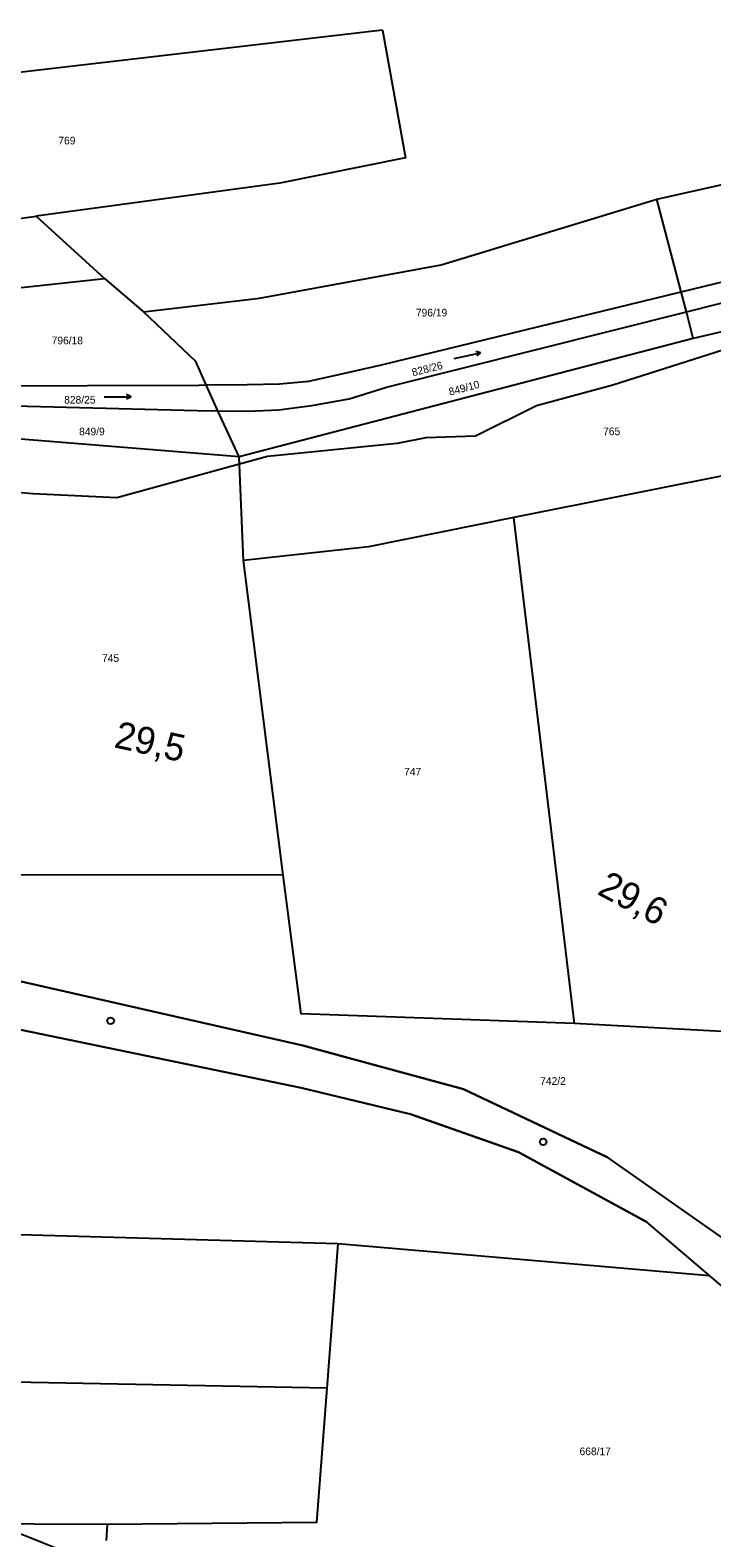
# Model space of a CAD drawing. Extents: x -794765 to -785424, y -1118958 to -1108731.
# Drawn here: x -788796.9 to -788645.5, y -1114795.4 to -1114460.5 of the extents above; entities that cross this region are included whole.
import ezdxf

# ---------------------------------------------------------------- set-up
doc = ezdxf.new("R2010")
doc.units = 0
for name, color, linetype in [('Level 66', 7, 'Continuous'), ('Level 73', 7, 'Continuous'), ('Level 75', 7, 'Continuous'), ('Level 76', 7, 'Continuous'), ('Level 81', 7, 'Continuous'), ('Vrstva 1', 7, 'Continuous'), ('Vrstva 53', 7, 'Continuous')]:
    doc.layers.add(name, color=color, linetype=linetype)

msp = doc.modelspace()

# ---------------------------------------------------------------- linework, layer by layer
at = {"layer": 'Level 66'}
for p, q in [((-788702.69, -1114533.48), (-788696.82, -1114532.23)), ((-788696.82, -1114532.23), (-788697.88, -1114531.94)), ((-788696.82, -1114532.23), (-788697.67, -1114532.93)), ((-788780.48, -1114541.97), (-788774.48, -1114541.97)), ((-788774.48, -1114541.97), (-788775.46, -1114541.47)), ((-788774.48, -1114541.97), (-788775.46, -1114542.47))]:
    msp.add_line(p, q, dxfattribs=at)
at = {"layer": 'Level 75'}
for p, q in [((-788657.65, -1114498.07), (-788604.55, -1114486.18)), ((-788652.28, -1114518.65), (-788657.65, -1114498.07)), ((-788795.54, -1114501.83), (-788780.41, -1114515.68)), ((-788780.41, -1114515.68), (-788771.75, -1114523.06)), ((-788651.12, -1114523.09), (-788652.28, -1114518.65)), ((-788602.26, -1114517.95), (-788649.58, -1114529.02)), ((-788649.58, -1114529.02), (-788651.12, -1114523.09)), ((-788649.58, -1114529.02), (-788750.44, -1114555.28)), ((-788755.23, -1114545.05), (-788757.8, -1114539.34)), ((-788750.44, -1114555.28), (-788755.23, -1114545.05)), ((-788750.44, -1114555.28), (-788812.08, -1114550.36)), ((-788593.73, -1114549.62), (-788689.42, -1114568.81)), ((-788749.5, -1114578.32), (-788750.44, -1114555.28)), ((-788676.01, -1114681.19), (-788689.42, -1114568.81)), ((-788740.67, -1114648.25), (-788749.5, -1114578.32)), ((-788740.67, -1114648.25), (-788809.85, -1114648.14)), ((-788578.67, -1114686.45), (-788676.01, -1114681.19)), ((-788728.52, -1114730.08), (-788889.17, -1114725.56)), ((-788728.52, -1114730.08), (-788730.98, -1114762.14)), ((-788646.02, -1114737.19), (-788728.52, -1114730.08)), ((-788730.98, -1114762.14), (-788891.11, -1114759.07)), ((-788779.95, -1114796.03), (-788779.75, -1114792.43))]:
    msp.add_line(p, q, dxfattribs=at)
for points in [[(-788718.63, -1114460.53), (-788817.27, -1114472.02), (-788860.22, -1114476)], [(-788718.63, -1114460.53), (-788713.48, -1114488.88), (-788741.43, -1114494.53), (-788795.54, -1114501.83)], [(-788652.28, -1114518.65), (-788624.54, -1114511.9), (-788617.46, -1114509.39), (-788611.73, -1114507.29), (-788607.29, -1114504.53), (-788603.63, -1114501.82), (-788598.93, -1114496.8), (-788594.19, -1114490.76), (-788587.23, -1114480)], [(-788651.12, -1114523.09), (-788623.58, -1114516.16), (-788616, -1114514.07), (-788610.11, -1114511.52), (-788604.65, -1114507.97), (-788600.76, -1114505.15), (-788595.29, -1114500.07), (-788590.4, -1114494.22), (-788581.92, -1114481.24), (-788580.1, -1114477.46)], [(-788860.65, -1114495.76), (-788860.57, -1114507.36), (-788820.58, -1114505.34), (-788795.54, -1114501.83)], [(-788771.75, -1114523.06), (-788745.95, -1114520.06), (-788705.61, -1114512.65), (-788657.65, -1114498.07)], [(-788812.75, -1114539.42), (-788813.99, -1114519.29), (-788780.41, -1114515.68)], [(-788757.8, -1114539.34), (-788748.69, -1114539.26), (-788741.49, -1114539.08), (-788735.01, -1114538.51), (-788727.34, -1114536.81), (-788718.84, -1114534.86), (-788652.28, -1114518.65)], [(-788757.8, -1114539.34), (-788760.13, -1114534.14), (-788771.75, -1114523.06)], [(-788755.23, -1114545.05), (-788748.54, -1114545.13), (-788741.64, -1114544.89), (-788734.31, -1114543.93), (-788726.02, -1114542.39), (-788717.73, -1114539.86), (-788651.12, -1114523.09)], [(-788812.75, -1114539.42), (-788809.05, -1114539.56), (-788759.42, -1114539.35), (-788757.8, -1114539.34)], [(-788812.49, -1114543.63), (-788809.16, -1114543.75), (-788759.81, -1114544.99), (-788755.23, -1114545.05)], [(-788689.42, -1114568.81), (-788721.73, -1114575.26), (-788749.5, -1114578.32)], [(-788676.01, -1114681.19), (-788736.73, -1114679), (-788740.67, -1114648.25)], [(-788630.19, -1114737.89), (-788640.82, -1114730.42), (-788668.56, -1114710.95), (-788700.64, -1114695.78), (-788736.3, -1114686.03), (-788817.52, -1114667.59)], [(-788818.39, -1114678.6), (-788736.68, -1114695.45), (-788712.4, -1114701.34), (-788688.38, -1114709.77), (-788660.09, -1114725.18), (-788646.02, -1114737.19)], [(-788646.02, -1114737.19), (-788635.61, -1114746.08), (-788616.47, -1114768.17)], [(-788730.98, -1114762.14), (-788733.28, -1114792.03), (-788779.75, -1114792.43)], [(-788779.75, -1114792.43), (-788828.56, -1114792.24), (-788890.53, -1114788.77)]]:
    msp.add_lwpolyline(points, dxfattribs=at)
at = {"layer": 'Level 81'}
for points in [[(-788641.17, -1114531.05), (-788667.46, -1114539.39), (-788684.41, -1114543.99), (-788697.98, -1114550.72), (-788708.99, -1114551.11), (-788715.35, -1114552.35), (-788744.16, -1114555.22), (-788750.37, -1114556.93), (-788777.65, -1114564.42), (-788796.29, -1114563.51), (-788811.71, -1114562.17)], [(-789061.76, -1114798.86), (-789055.53, -1114793.64), (-789048.32, -1114789.44), (-789035.18, -1114782.71), (-789024.16, -1114779.36), (-789001.7, -1114774.78), (-788981.9, -1114772.16), (-788976.7, -1114771.48), (-788957.63, -1114771.54), (-788907.65, -1114776.78), (-788896.06, -1114778.62), (-788892.28, -1114779.23), (-788858.94, -1114784.55), (-788838.18, -1114786.31), (-788830.99, -1114788.02), (-788814.89, -1114790.61), (-788807.51, -1114792.32), (-788800.07, -1114794.04), (-788785.25, -1114800.01)]]:
    msp.add_lwpolyline(points, dxfattribs=at)
at = {"layer": 'Vrstva 1'}
for centre in [(-788779.02, -1114680.58), (-788682.93, -1114707.45)]:
    msp.add_circle(centre, 0.75, dxfattribs=at)
at = {"layer": 'Vrstva 53'}
for points in [[(-788660.09, -1114725.18), (-788688.38, -1114709.77), (-788712.4, -1114701.34), (-788736.68, -1114695.45), (-788818.39, -1114678.6), (-788821.94, -1114677.87), (-788898.55, -1114660.57), (-788962.34, -1114647.14), (-789033.04, -1114632.27), (-789062.17, -1114626.14), (-789068.5, -1114624.81), (-789075.07, -1114623.43), (-789124.89, -1114611.37)], [(-788817.52, -1114667.59), (-788736.3, -1114686.03), (-788700.64, -1114695.78), (-788668.56, -1114710.95)]]:
    msp.add_lwpolyline(points, dxfattribs=at)

# ---------------------------------------------------------------- texts
at = {"layer": 'Level 73'}
for s, rotation, p in [('29,5', 347.6604, (-788778.48, -1114619.79)), ('29,6', 332.1118, (-788671.18, -1114652.33))]:
    msp.add_text(s, height=6, rotation=rotation, dxfattribs=at).set_placement(p)
at = {"layer": 'Level 76'}
for s, p in [('769', (-788790.64, -1114485.91)), ('796/19', (-788711.2, -1114524.12)), ('796/18', (-788792.12, -1114530.31)), ('828/25', (-788789.34, -1114543.47)), ('849/9', (-788786.02, -1114550.53)), ('765', (-788669.61, -1114550.49)), ('745', (-788780.93, -1114600.85)), ('747', (-788713.82, -1114626.08)), ('742/2', (-788683.59, -1114694.79)), ('668/17', (-788674.85, -1114777.05))]:
    msp.add_text(s, height=1.7, dxfattribs=at).set_placement(p)
for s, rotation, p in [('828/26', 14, (-788711.86, -1114537.42)), ('849/10', 15, (-788703.64, -1114541.73))]:
    msp.add_text(s, height=1.7, rotation=rotation, dxfattribs=at).set_placement(p)

doc.saveas('drawing.dxf')
